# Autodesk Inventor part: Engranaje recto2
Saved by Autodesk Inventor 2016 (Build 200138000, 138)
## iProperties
Created: 2016-06
Part Number: Engranaje recto2
Material: Steel
Document SubType Name: Modeling
Designer: adm
Categories: <?xml version="1.0" encoding="UTF-16"?> <MemberInstance><Categories><FamilyTemplate><FamilyTemplateParameter ValueType="xs:double" Id="1" ObjectReferenceKey="da
Density: 1 g/cm^3
Appearance: Steel
CustomPartVersion: 1
Author: adm
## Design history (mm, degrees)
sketch "Sketch1"
  geometry: C1 r 59 at (0, 0)
  constraints: 1 centre point
  dimensions: "d0" = 118 diameter of C1 (= da_da)
extrude "Extrusion1" new body sketch "Sketch1" distance "d1" = 20 (= da_b); taper "d2" = 0 deg
workplane "Work Plane2"
sketch "Sketch2"
  geometry: C1 r 59 at (0, 0) reference; C2 r 57 at (0, 0)
  constraints: 1 centre point, 1 coincident
  dimensions: "d3" = 114 diameter of C2 (= da_dw)
feature "Diámetro de separación" sketch "Sketch2" dims "d4" = 10, "d5" = 0
workplane "Work Plane8"
workplane "Work Plane9"
feature "Engranaje recto" dims "d5" = 0, "da_b" = 20, "da_d" = 114, "da_aw" = 80, "da_da" = 118, "da_df" = 109, "da_dw" = 114, angle "da_beta" = 0 deg, "da_lefttooth" = 0, "da_righttooth" = 0
body "Solid1"
body "Srf1"
other parameters: "d17" = 0, "d34" = 0.55116 (computed from da_z), "d39" = 0, "d41" = 0, "d47" = 0, "d48" = 0
